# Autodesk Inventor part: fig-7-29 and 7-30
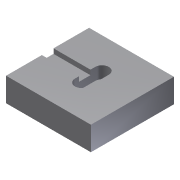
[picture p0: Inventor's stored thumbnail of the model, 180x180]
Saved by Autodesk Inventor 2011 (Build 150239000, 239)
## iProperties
Created: 2004-05
Part Number: fig-7-29 and 7-30
Document SubType Name: Modeling
Designer: CADCIM Technologies
Manufacturer: Standard
Standards Organization: Custom
Density: 1 g/cm^3
Author: CADCIM Technologies
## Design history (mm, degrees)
sketch "Sketch1"
  geometry: L1 (-30.233, -25.517)-(22.302, -25.517); L2 (22.302, -25.517)-(22.302, 25.904); L3 (22.302, 25.904)-(-30.233, 25.904); L4 (-30.233, 25.904)-(-30.233, -25.517)
  constraints: 8 end point, 2 parallel, 1 horizontal, 1 perpendicular
extrude "Extrusion1" new body sketch "Sketch1" distance "d0" = 14.75; taper "d1" = 0 deg
sketch "Sketch2"
  geometry: L1 (1.047, -5.75)-(1.047, 6.846); L2 (-7.35, 6.845)-(-7.35, -5.75); A1 r 4.198 centre (-3.152, 6.846) between (1.047, 6.846) and (-7.35, 6.845); A2 r 4.198 centre (-3.152, -5.75) between (-7.35, -5.75) and (1.047, -5.75)
  constraints: 4 end point, 4 point on circle, 4 tangent, 2 centre point, 1 parallel
extrude "Extrusion2" cut sketch "Sketch2" distance "d2" = 7.5; taper "d3" = 0 deg
sketch "Sketch3"
  geometry: L1 (-7.5, 0)-(-7.5, 12.595) reference; L2 (-7.5, 0)-(0, 0) reference; L3 (-7.5, 2.416)-(-4.537, 2.416); L4 (-4.537, 2.416)-(-4.537, 9.616); L5 (-4.537, 9.616)-(-7.5, 9.616)
  constraints: 6 end point, 2 perpendicular, 2 point on line, 1 parallel
extrude "Extrusion3" cut sketch "Sketch3" stored distance "d4" = 6.75; taper "d5" = 0 deg
body "Solid1"
